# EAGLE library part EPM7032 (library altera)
EPM7032 MAX 7000 family
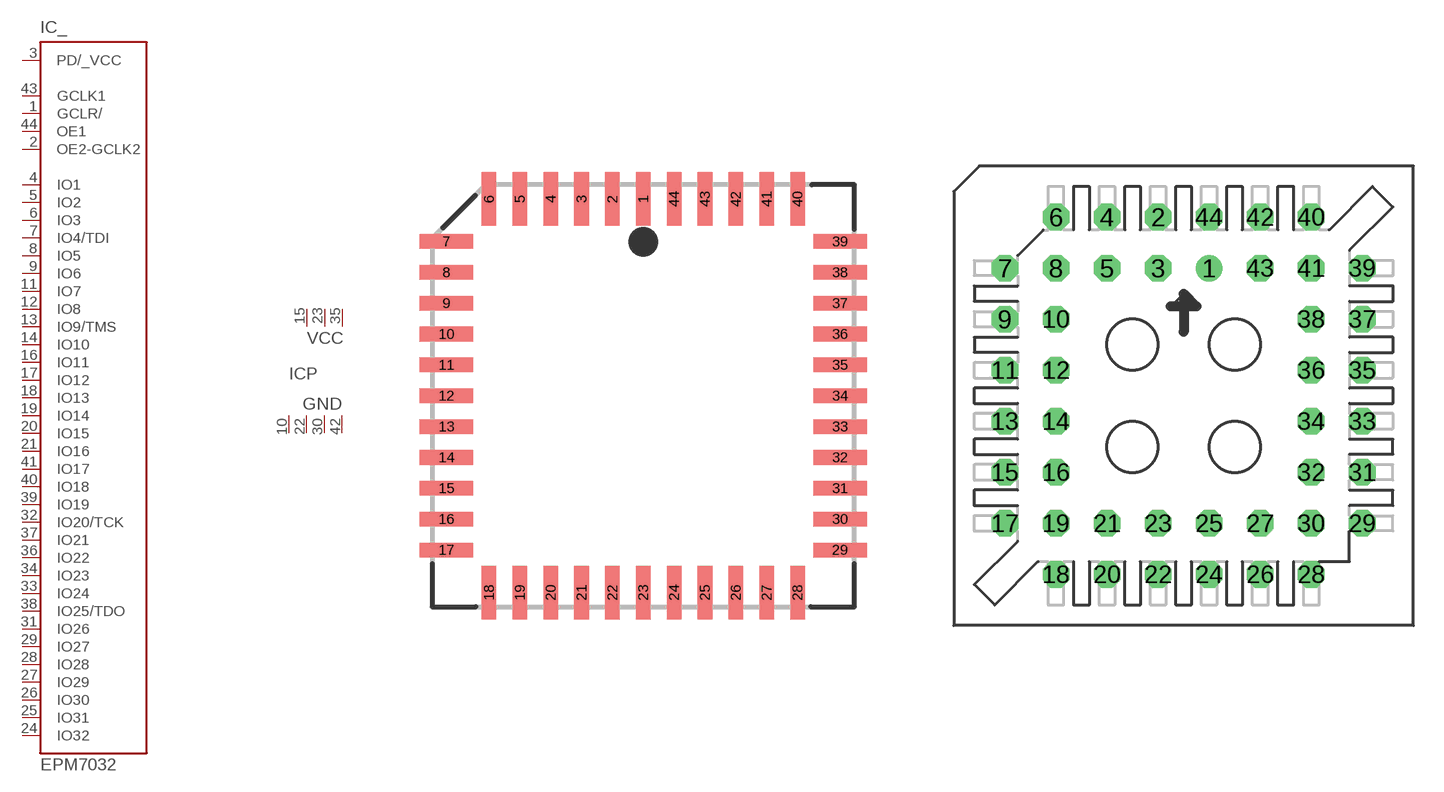
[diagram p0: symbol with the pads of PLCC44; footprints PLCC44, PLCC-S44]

Designator prefix IC; gates _=EPM7032 P=PWR3-4

## EPM7032J44 (OC_FARNELL: unknown; OC_NEWARK: unknown)  [PLCC44]
1  _:GCLR/  in
2  _:OE2-GCLK2  in
3  _:PD/_VCC  pas
4  _:IO1
5  _:IO2
6  _:IO3
7  _:IO4/TDI
8  _:IO5
9  _:IO6
10  P:GND  pwr
11  _:IO7
12  _:IO8
13  _:IO9/TMS
14  _:IO10
15  P:VCC  pwr
16  _:IO11
17  _:IO12
18  _:IO13
19  _:IO14
20  _:IO15
21  _:IO16
22  P:GND  pwr
23  P:VCC  pwr
24  _:IO32
25  _:IO31
26  _:IO30
27  _:IO29
28  _:IO28
29  _:IO27
30  P:GND  pwr
31  _:IO26
32  _:IO20/TCK
33  _:IO24
34  _:IO23
35  P:VCC  pwr
36  _:IO22
37  _:IO21
38  _:IO25/TDO
39  _:IO19
40  _:IO18
41  _:IO17
42  P:GND  pwr
43  _:GCLK1  in
44  _:OE1  in

## EPM7032S44 (MPN: EPM7032SLC44-6N; OC_FARNELL: 1549447; OC_NEWARK: 51R9532)  [PLCC-S44]
Pads as for PLCC44

## EPM7032T44 (MPN: EPM7032SLC44-6N; OC_FARNELL: 1549447; OC_NEWARK: 51R9532)  [TQFP44]
1  _:IO4/TDI
2  _:IO5
3  _:IO6
4  P:GND  pwr
5  _:IO7
6  _:IO8
7  _:IO9/TMS
8  _:IO10
9  P:VCC  pwr
10  _:IO11
11  _:IO12
12  _:IO13
13  _:IO14
14  _:IO15
15  _:IO16
16  P:GND  pwr
17  P:VCC  pwr
18  _:IO32
19  _:IO31
20  _:IO30
21  _:IO29
22  _:IO28
23  _:IO27
24  P:GND  pwr
25  _:IO26
26  _:IO20/TCK
27  _:IO24
28  _:IO23
29  P:VCC  pwr
30  _:IO22
31  _:IO21
32  _:IO25/TDO
33  _:IO19
34  _:IO18
35  _:IO17
36  P:GND  pwr
37  _:GCLK1  in
38  _:OE1  in
39  _:GCLR/  in
40  _:OE2-GCLK2  in
41  _:PD/_VCC  pas
42  _:IO1
43  _:IO2
44  _:IO3

## Footprint PLCC44 (pad centres in mm)
Plastic J-Lead Chip Carrier
smd 0.6 x 2.2: 1 0,8.1; 2 -1.27,8.1; 3 -2.54,8.1; 4 -3.81,8.1; 5 -5.08,8.1; 6 -6.35,8.1; 18 -6.35,-8.1; 19 -5.08,-8.1; 20 -3.81,-8.1; 21 -2.54,-8.1; 22 -1.27,-8.1; 23 0,-8.1; 24 1.27,-8.1; 25 2.54,-8.1; 26 3.81,-8.1; 27 5.08,-8.1; 28 6.35,-8.1; 40 6.35,8.1; 41 5.08,8.1; 42 3.81,8.1; 43 2.54,8.1; 44 1.27,8.1
smd 2.2 x 0.6: 7 -8.1,6.35; 8 -8.1,5.08; 9 -8.1,3.81; 10 -8.1,2.54; 11 -8.1,1.27; 12 -8.1,0; 13 -8.1,-1.27; 14 -8.1,-2.54; 15 -8.1,-3.81; 16 -8.1,-5.08; 17 -8.1,-6.35; 29 8.1,-6.35; 30 8.1,-5.08; 31 8.1,-3.81; 32 8.1,-2.54; 33 8.1,-1.27; 34 8.1,0; 35 8.1,1.27; 36 8.1,2.54; 37 8.1,3.81; 38 8.1,5.08; 39 8.1,6.35

## Footprint PLCC-S44 (pad centres in mm)
Plastic Leaded Chip Carrier Socked
drill 0.813 round: 1 1.27,6.35
drill 0.813 octagon: 2 -1.27,8.89; 3 -1.27,6.35; 4 -3.81,8.89; 5 -3.81,6.35; 6 -6.35,8.89; 7 -8.89,6.35; 8 -6.35,6.35; 9 -8.89,3.81; 10 -6.35,3.81; 11 -8.89,1.27; 12 -6.35,1.27; 13 -8.89,-1.27; 14 -6.35,-1.27; 15 -8.89,-3.81; 16 -6.35,-3.81; 17 -8.89,-6.35; 18 -6.35,-8.89; 19 -6.35,-6.35; 20 -3.81,-8.89; 21 -3.81,-6.35; 22 -1.27,-8.89; 23 -1.27,-6.35; 24 1.27,-8.89; 25 1.27,-6.35; 26 3.81,-8.89; 27 3.81,-6.35; 28 6.35,-8.89; 29 8.89,-6.35; 30 6.35,-6.35; 31 8.89,-3.81; 32 6.35,-3.81; 33 8.89,-1.27; 34 6.35,-1.27; 35 8.89,1.27; 36 6.35,1.27; 37 8.89,3.81; 38 6.35,3.81; 39 8.89,6.35; 40 6.35,8.89; 41 6.35,6.35; 42 3.81,8.89; 43 3.81,6.35; 44 1.27,8.89

## Footprint TQFP44 (pad centres in mm)
Plastic Thin Quad Flat Pack
smd 1.5 x 0.5: 1 -5.8,4; 2 -5.8,3.2; 3 -5.8,2.4; 4 -5.8,1.6; 5 -5.8,0.8; 6 -5.8,0; 7 -5.8,-0.8; 8 -5.8,-1.6; 9 -5.8,-2.4; 10 -5.8,-3.2; 11 -5.8,-4; 23 5.8,-4; 24 5.8,-3.2; 25 5.8,-2.4; 26 5.8,-1.6; 27 5.8,-0.8; 28 5.8,0; 29 5.8,0.8; 30 5.8,1.6; 31 5.8,2.4; 32 5.8,3.2; 33 5.8,4
smd 0.5 x 1.5: 12 -4,-5.8; 13 -3.2,-5.8; 14 -2.4,-5.8; 15 -1.6,-5.8; 16 -0.8,-5.8; 17 0,-5.8; 18 0.8,-5.8; 19 1.6,-5.8; 20 2.4,-5.8; 21 3.2,-5.8; 22 4,-5.8; 34 4,5.8; 35 3.2,5.8; 36 2.4,5.8; 37 1.6,5.8; 38 0.8,5.8; 39 0,5.8; 40 -0.8,5.8; 41 -1.6,5.8; 42 -2.4,5.8; 43 -3.2,5.8; 44 -4,5.8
